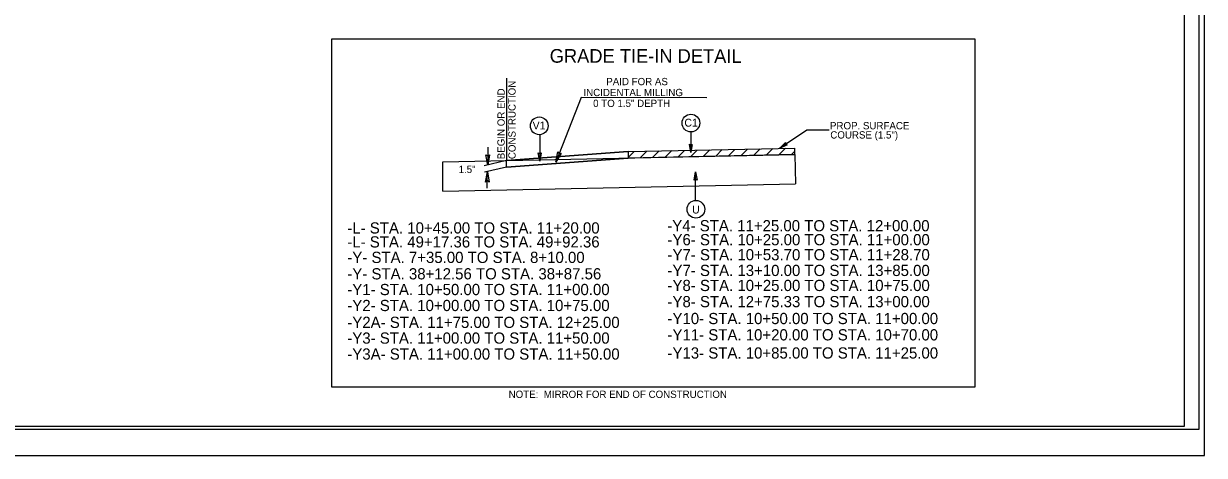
# Model space of a CAD drawing. Extents: x 958711 to 962106, y 831169 to 840840.
# Drawn here: x 959380 to 960395, y 832394 to 832765 of the extents above; entities that cross this region are included whole.
import ezdxf

# ---------------------------------------------------------------- set-up
doc = ezdxf.new("R2010")
doc.units = 0
for name, color, linetype in [('Default', 7, 'Continuous'), ('Old_Level_1', 7, 'Continuous'), ('Prop Dimension', 7, 'Continuous'), ('Prop Dimension Text', 7, 'Continuous'), ('Sheet Plot Border Inside CELL', 7, 'Continuous'), ('Sheet Plot Border Outside CELL', 7, 'Continuous'), ('Sheet Typical CELL', 7, 'Continuous'), ('Typical ID Circle CELL', 7, 'Continuous'), ('Typical Pavement Slope CELL', 7, 'Continuous'), ('Typical Terminator CELL', 7, 'Continuous'), ('Typical Text ID Circle CELL', 7, 'Continuous')]:
    doc.layers.add(name, color=color, linetype=linetype)

msp = doc.modelspace()

# ---------------------------------------------------------------- linework, layer by layer
at = {"layer": 'Old_Level_1'}
for p, q in [((959899.6, 832649.6), (959904.8, 832654.8)), ((959909.9, 832649.3), (959915.6, 832655)), ((959920.7, 832649.5), (959926.4, 832655.2)), ((959931.6, 832649.8), (959937.3, 832655.5)), ((959942.4, 832650), (959948.1, 832655.7)), ((959953.4, 832650.3), (959958.9, 832655.9)), ((959964.1, 832650.5), (959969.8, 832656.1)), ((959974.9, 832650.7), (959980.6, 832656.4)), ((959985.9, 832651.1), (959991.4, 832656.6)), ((959996.6, 832651.1), (960002.3, 832656.8)), ((960007.4, 832651.4), (960013.1, 832657)), ((960018.2, 832651.6), (960023.9, 832657.3)), ((960029.1, 832651.8), (960034.8, 832657.5)), ((960039.9, 832652.1), (960043, 832655.1))]:
    msp.add_line(p, q, dxfattribs=at)
for points in [[(959645.2, 832751.4), (960197.6, 832751.4), (960197.6, 832452.4), (959645.2, 832452.4)], [(959795.1, 832646.9), (959899.6, 832654.7), (959899.6, 832649.1), (959795.1, 832641.4)]]:
    msp.add_lwpolyline(points, close=True, dxfattribs=at)
at = {"layer": 'Prop Dimension'}
for p, q in [((959795.1, 832717.6), (959795.1, 832646.9)), ((959779, 832658.4), (959779, 832643.1)), ((959795.1, 832646.9), (959776.1, 832642.4)), ((959795.1, 832641.4), (959776.3, 832636.9)), ((959778.6, 832623.2), (959778.6, 832637.5))]:
    msp.add_line(p, q, dxfattribs=at)
for points in [[(959967.3, 832700.8), (959859.2, 832701), (959837.5, 832645.7)], [(960072.4, 832673), (960053.3, 832673), (960029.6, 832657.4)]]:
    msp.add_lwpolyline(points, dxfattribs=at)
at = {"layer": 'Sheet Plot Border Inside CELL'}
msp.add_lwpolyline([(960390.3, 833471.3), (958723.8, 833471.3), (958723.8, 832416.2), (960390.3, 832416.2)], close=True, dxfattribs=at)
at = {"layer": 'Sheet Plot Border Outside CELL'}
msp.add_lwpolyline([(960394.8, 833493.8), (958710.8, 833493.8), (958710.8, 832393.8), (960394.8, 832393.8)], close=True, dxfattribs=at)
at = {"layer": 'Sheet Typical CELL'}
msp.add_lwpolyline([(960377.8, 833468.8), (958877.8, 833468.8), (958877.8, 832418.8), (960377.8, 832418.8)], close=True, dxfattribs=at)
at = {"layer": 'Typical ID Circle CELL'}
for points in [[(959823.7, 832669.2), (959823.7, 832648)], [(959953.6, 832671.6), (959953.6, 832656)], [(959957.5, 832612.7), (959957.5, 832635)]]:
    msp.add_lwpolyline(points, dxfattribs=at)
for points in [[(959824.9, 832653.6), (959823.7, 832646.4), (959822.4, 832653.6), (959823.7, 832652.7)], [(959954.8, 832660.9), (959953.6, 832653.8), (959952.3, 832661), (959953.6, 832660.1)], [(960036.2, 832660.4), (960029.6, 832657.4), (960034.8, 832662.5), (960034.8, 832660.9)]]:
    msp.add_lwpolyline(points, close=True, dxfattribs=at)
for centre in [(959823.3, 832676.8), (959953.6, 832679.2), (959957.9, 832605.1)]:
    msp.add_circle(centre, 7.6, dxfattribs=at)
at = {"layer": 'Typical Pavement Slope CELL'}
for p, q in [((959899.6, 832654.7), (959795.1, 832646.9)), ((959899.6, 832654.7), (960043, 832657.7)), ((960043, 832652.1), (960043, 832657.7)), ((959740.4, 832620.7), (959740.5, 832645.8)), ((959740.5, 832645.8), (960043, 832652.1)), ((959795.1, 832641.4), (959899.6, 832649.1)), ((959795.1, 832641.4), (959899.6, 832649.1)), ((959899.6, 832649.1), (959795.1, 832641.4)), ((960043, 832652.1), (959899.6, 832649.1)), ((960043, 832652.1), (960043.5, 832627.1)), ((959740.5, 832620.8), (960043.5, 832627.1))]:
    msp.add_line(p, q, dxfattribs=at)
msp.add_lwpolyline([(959956.4, 832630), (959957.6, 832637.2), (959959, 832630), (959957.7, 832630.9)], close=True, dxfattribs=at)
at = {"layer": 'Typical Terminator CELL'}
for points in [[(959842.2, 832653.4), (959837.5, 832645.7), (959839.3, 832654.6), (959840.3, 832653)], [(959780.6, 832652), (959779, 832643.1), (959777.5, 832652), (959779, 832650.9)], [(959777.2, 832628.4), (959778.7, 832637.3), (959780.3, 832628.4), (959778.7, 832629.5)]]:
    msp.add_lwpolyline(points, close=True, dxfattribs=at)

# ---------------------------------------------------------------- texts
at = {"layer": 'Default'}
msp.add_text('GRADE TIE-IN DETAIL', height=11.739, rotation=359.9469, dxfattribs=at).set_placement((959832.3, 832731))
for s, p in [('-L- STA. 10+45.00 TO STA. 11+20.00', (959658.4, 832584.3)), ('-Y4- STA. 11+25.00 TO STA. 12+00.00', (959933.3, 832586.2)), ('-L- STA. 49+17.36 TO STA. 49+92.36', (959658.4, 832572.3)), ('-Y6- STA. 10+25.00 TO STA. 11+00.00', (959933.5, 832574.2)), ('-Y- STA. 7+35.00 TO STA. 8+10.00', (959658.4, 832559)), ('-Y7- STA. 10+53.70 TO STA. 11+28.70', (959933.5, 832561.3)), ('-Y- STA. 38+12.56 TO STA. 38+87.56', (959658.4, 832544.9)), ('-Y7- STA. 13+10.00 TO STA. 13+85.00', (959933.5, 832547.8)), ('-Y1- STA. 10+50.00 TO STA. 11+00.00', (959658.4, 832531.4)), ('-Y8- STA. 10+25.00 TO STA. 10+75.00', (959933.5, 832534.9)), ('-Y8- STA. 12+75.33 TO STA. 13+00.00', (959933.5, 832521)), ('-Y2- STA. 10+00.00 TO STA. 10+75.00', (959658.4, 832517.7)), ('-Y2A- STA. 11+75.00 TO STA. 12+25.00', (959658.4, 832503.2)), ('-Y10- STA. 10+50.00 TO STA. 11+00.00', (959933.5, 832506.5)), ('-Y11- STA. 10+20.00 TO STA. 10+70.00', (959933.5, 832492.5)), ('-Y3- STA. 11+00.00 TO STA. 11+50.00', (959658.4, 832489.7)), ('-Y3A- STA. 11+00.00 TO STA. 11+50.00', (959658.4, 832476)), ('-Y13- STA. 10+85.00 TO STA. 11+25.00', (959933.5, 832476.9))]:
    msp.add_text(s, height=9.625, dxfattribs=at).set_placement(p)
at = {"layer": 'Prop Dimension Text'}
for s, rotation, p in [('CONSTRUCTION', 90, (959803, 832648.2)), ('PAID FOR AS ', 360, (959880.9, 832711.7)), ('BEGIN OR END', 90, (959793.6, 832648.1)), ('INCIDENTAL MILLING', 360, (959861.3, 832702.3)), ('0 TO 1.5" DEPTH', 360, (959869.6, 832693)), ('PROP. SURFACE ', 360, (960073.1, 832673.8)), ('COURSE (1.5")', 360, (960073.4, 832665.9)), ('1.5"', 360, (959754, 832636.3)), ('NOTE:  MIRROR FOR END OF CONSTRUCTION', 360, (959797, 832443.1))]:
    msp.add_text(s, height=6.25, rotation=rotation, dxfattribs=at).set_placement(p)
at = {"layer": 'Typical Text ID Circle CELL'}
for s, p in [('C1', (959948, 832676.1)), ('V1', (959817.6, 832673.7)), ('U', (959954.6, 832601.5))]:
    msp.add_text(s, height=6.79, dxfattribs=at).set_placement(p)

doc.saveas('drawing.dxf')
